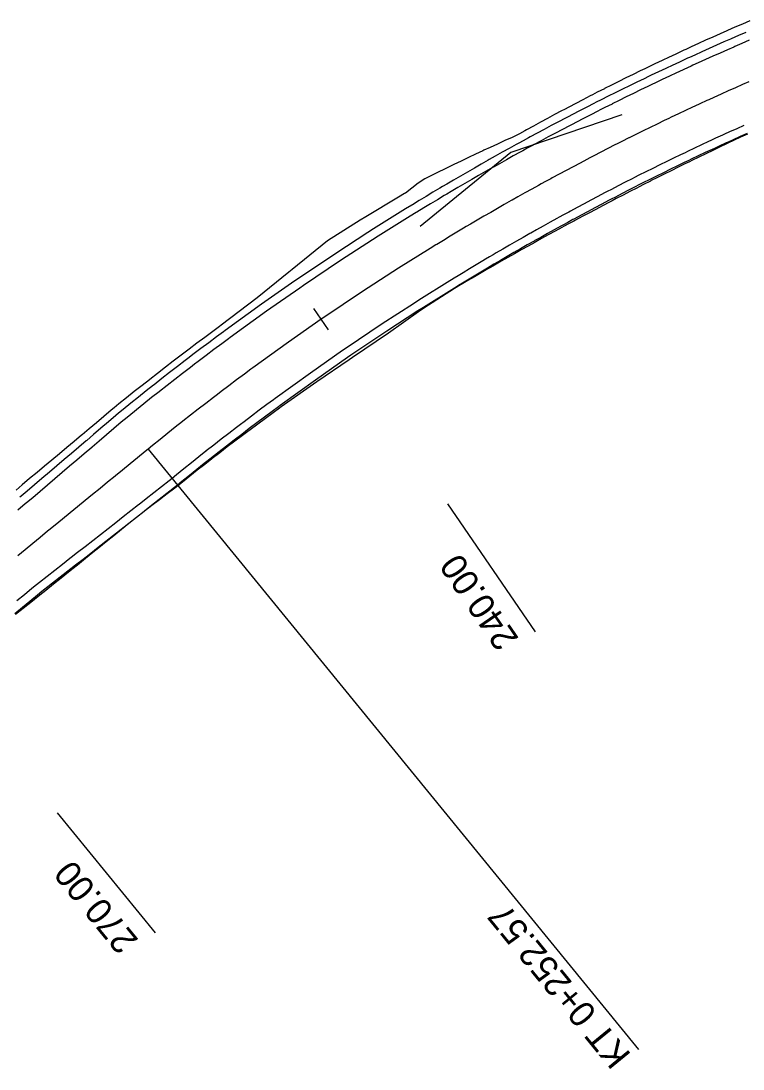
# Model space of a CAD drawing. Extents: x -550605 to -538780, y -1102367 to -1093705.
# Drawn here: x -546697.9 to -546656, y -1100798.1 to -1100737.2 of the extents above; entities that cross this region are included whole.
import ezdxf

# ---------------------------------------------------------------- set-up
doc = ezdxf.new("R2010")
doc.units = 0
for name, color, linetype in [('SIT - horní hrana zářezu', 7, 'Continuous'), ('SIT - hrany vozovky', 7, 'Continuous'), ('SIT - osa cesty', 7, 'Continuous'), ('SIT - paty násypů', 7, 'Continuous'), ('SIT - poloměry oblouků', 7, 'Continuous'), ('SIT - staničení hlavních bodů', 7, 'Continuous'), ('SIT - staničení po 30m', 7, 'Continuous')]:
    doc.layers.add(name, color=color, linetype=linetype)

msp = doc.modelspace()

# ---------------------------------------------------------------- linework, layer by layer
at = {"layer": 'SIT - horní hrana zářezu'}
msp.add_lwpolyline([(-546672.732, -1100752.748), (-546674.519, -1100753.888), (-546674.825, -1100754.101), (-546676.572, -1100755.346), (-546678.653, -1100756.758), (-546678.859, -1100756.895), (-546680.737, -1100758.166), (-546682.793, -1100759.616), (-546682.893, -1100759.688), (-546683.273, -1100759.963), (-546683.719, -1100760.289), (-546684.163, -1100760.616), (-546684.606, -1100760.945), (-546684.821, -1100761.106), (-546685.048, -1100761.276), (-546685.488, -1100761.608), (-546685.928, -1100761.942), (-546686.366, -1100762.278), (-546686.802, -1100762.616), (-546686.82, -1100762.63), (-546686.822, -1100762.632), (-546687.237, -1100762.955), (-546687.671, -1100763.296), (-546688.104, -1100763.639), (-546688.535, -1100763.983), (-546688.796, -1100764.193), (-546688.972, -1100764.328), (-546689.419, -1100764.669), (-546689.866, -1100765.01), (-546690.314, -1100765.351), (-546690.732, -1100765.67), (-546690.761, -1100765.692)], dxfattribs=at)
at = {"layer": 'SIT - hrany vozovky'}
for points in [[(-546655.619, -1100738.343), (-546656.044, -1100738.526), (-546656.468, -1100738.711), (-546656.517, -1100738.732), (-546656.892, -1100738.896), (-546657.315, -1100739.083), (-546657.737, -1100739.272), (-546658.159, -1100739.461), (-546658.581, -1100739.652), (-546658.892, -1100739.794), (-546659.001, -1100739.844), (-546659.422, -1100740.037), (-546659.713, -1100740.172), (-546659.841, -1100740.232), (-546660.26, -1100740.428), (-546660.678, -1100740.625), (-546661.096, -1100740.824), (-546661.248, -1100740.896), (-546661.513, -1100741.023), (-546661.93, -1100741.224), (-546662.346, -1100741.427), (-546662.761, -1100741.63), (-546663.176, -1100741.835), (-546663.585, -1100742.038), (-546663.59, -1100742.041), (-546664.004, -1100742.248), (-546664.277, -1100742.386), (-546664.416, -1100742.457), (-546664.829, -1100742.667), (-546665.24, -1100742.878), (-546665.651, -1100743.09), (-546665.903, -1100743.221), (-546666.061, -1100743.303), (-546666.471, -1100743.518), (-546666.88, -1100743.734), (-546667.288, -1100743.952), (-546667.696, -1100744.17), (-546668.103, -1100744.39), (-546668.199, -1100744.442), (-546668.509, -1100744.611), (-546668.765, -1100744.751), (-546668.915, -1100744.833), (-546669.32, -1100745.057), (-546669.724, -1100745.281), (-546670.128, -1100745.507), (-546670.475, -1100745.703), (-546670.531, -1100745.734), (-546670.933, -1100745.963), (-546671.334, -1100746.192), (-546671.735, -1100746.423), (-546672.135, -1100746.655), (-546672.535, -1100746.888), (-546672.729, -1100747.002), (-546672.933, -1100747.123), (-546673.172, -1100747.264), (-546673.331, -1100747.358), (-546673.729, -1100747.595), (-546674.125, -1100747.833), (-546674.521, -1100748.073), (-546674.916, -1100748.313), (-546674.96, -1100748.34), (-546675.311, -1100748.555), (-546677.168, -1100749.715), (-546677.493, -1100749.923), (-546679.352, -1100751.129), (-546681.511, -1100752.579), (-546681.723, -1100752.724), (-546683.646, -1100754.066), (-546685.755, -1100755.589), (-546685.857, -1100755.664), (-546686.247, -1100755.953), (-546686.705, -1100756.294), (-546687.161, -1100756.636), (-546687.616, -1100756.98), (-546687.837, -1100757.148), (-546688.07, -1100757.326), (-546688.522, -1100757.673), (-546688.973, -1100758.023), (-546689.423, -1100758.373), (-546689.872, -1100758.726), (-546689.89, -1100758.741), (-546689.893, -1100758.743), (-546690.319, -1100759.08), (-546690.765, -1100759.436), (-546691.209, -1100759.794), (-546691.652, -1100760.153), (-546691.921, -1100760.372), (-546692.089, -1100760.515), (-546692.517, -1100760.88), (-546692.945, -1100761.244), (-546693.373, -1100761.609), (-546693.774, -1100761.95), (-546693.802, -1100761.973), (-546694.23, -1100762.338), (-546694.658, -1100762.703), (-546695.086, -1100763.067), (-546695.514, -1100763.432), (-546695.942, -1100763.796), (-546696.37, -1100764.161), (-546696.799, -1100764.525), (-546697.227, -1100764.89), (-546697.581, -1100765.192), (-546697.655, -1100765.255), (-546698.083, -1100765.619)], [(-546655.816, -1100737.884), (-546656.243, -1100738.068), (-546656.668, -1100738.252), (-546656.717, -1100738.274), (-546657.093, -1100738.439), (-546657.518, -1100738.626), (-546657.942, -1100738.815), (-546658.365, -1100739.005), (-546658.788, -1100739.197), (-546659.1, -1100739.339), (-546659.21, -1100739.389), (-546659.631, -1100739.583), (-546659.923, -1100739.719), (-546660.052, -1100739.779), (-546660.473, -1100739.975), (-546660.892, -1100740.173), (-546661.311, -1100740.372), (-546661.464, -1100740.445), (-546661.73, -1100740.573), (-546662.148, -1100740.774), (-546662.565, -1100740.977), (-546662.982, -1100741.181), (-546663.398, -1100741.387), (-546663.809, -1100741.591), (-546663.814, -1100741.594), (-546664.228, -1100741.802), (-546664.503, -1100741.94), (-546664.643, -1100742.011), (-546665.056, -1100742.221), (-546665.469, -1100742.433), (-546665.881, -1100742.646), (-546666.134, -1100742.777), (-546666.293, -1100742.86), (-546666.704, -1100743.076), (-546667.114, -1100743.293), (-546667.524, -1100743.511), (-546667.933, -1100743.73), (-546668.341, -1100743.95), (-546668.438, -1100744.003), (-546668.749, -1100744.172), (-546669.006, -1100744.313), (-546669.156, -1100744.395), (-546669.562, -1100744.619), (-546669.968, -1100744.845), (-546670.373, -1100745.071), (-546670.721, -1100745.268), (-546670.777, -1100745.299), (-546671.18, -1100745.528), (-546671.583, -1100745.759), (-546671.985, -1100745.99), (-546672.387, -1100746.223), (-546672.788, -1100746.457), (-546672.982, -1100746.571), (-546673.188, -1100746.692), (-546673.427, -1100746.834), (-546673.587, -1100746.929), (-546673.985, -1100747.166), (-546674.383, -1100747.405), (-546674.78, -1100747.645), (-546675.177, -1100747.886), (-546675.221, -1100747.913), (-546675.572, -1100748.129), (-546677.436, -1100749.293), (-546677.762, -1100749.501), (-546679.627, -1100750.711), (-546681.794, -1100752.166), (-546682.006, -1100752.311), (-546683.935, -1100753.658), (-546686.051, -1100755.186), (-546686.153, -1100755.262), (-546686.545, -1100755.551), (-546687.004, -1100755.893), (-546687.462, -1100756.237), (-546687.919, -1100756.582), (-546688.14, -1100756.75), (-546688.374, -1100756.929), (-546688.828, -1100757.277), (-546689.28, -1100757.628), (-546689.732, -1100757.98), (-546690.182, -1100758.334), (-546690.2, -1100758.348), (-546690.203, -1100758.35), (-546690.63, -1100758.689), (-546691.077, -1100759.046), (-546691.523, -1100759.405), (-546691.968, -1100759.765), (-546692.237, -1100759.985), (-546692.405, -1100760.128), (-546692.834, -1100760.493), (-546693.262, -1100760.857), (-546693.69, -1100761.222), (-546694.09, -1100761.563), (-546694.118, -1100761.586), (-546694.546, -1100761.951), (-546694.974, -1100762.316), (-546695.402, -1100762.68), (-546695.831, -1100763.045), (-546696.259, -1100763.409), (-546696.687, -1100763.774), (-546697.115, -1100764.138), (-546697.543, -1100764.503), (-546697.898, -1100764.805), (-546697.971, -1100764.868)], [(-546655.736, -1100743.744), (-546656.145, -1100743.928), (-546656.552, -1100744.112), (-546656.854, -1100744.25), (-546656.96, -1100744.298), (-546657.366, -1100744.486), (-546657.648, -1100744.616), (-546657.772, -1100744.674), (-546658.178, -1100744.864), (-546658.583, -1100745.054), (-546658.987, -1100745.246), (-546659.134, -1100745.317), (-546659.391, -1100745.44), (-546659.794, -1100745.634), (-546660.197, -1100745.83), (-546660.599, -1100746.027), (-546661, -1100746.225), (-546661.396, -1100746.422), (-546661.401, -1100746.425), (-546661.801, -1100746.625), (-546662.066, -1100746.759), (-546662.2, -1100746.827), (-546662.599, -1100747.03), (-546662.998, -1100747.234), (-546663.395, -1100747.44), (-546663.639, -1100747.566), (-546663.792, -1100747.646), (-546664.189, -1100747.854), (-546664.585, -1100748.063), (-546664.98, -1100748.274), (-546665.374, -1100748.485), (-546665.768, -1100748.698), (-546665.862, -1100748.749), (-546666.161, -1100748.912), (-546666.409, -1100749.047), (-546666.554, -1100749.127), (-546666.946, -1100749.343), (-546667.337, -1100749.561), (-546667.728, -1100749.779), (-546668.064, -1100749.969), (-546668.118, -1100749.999), (-546668.507, -1100750.22), (-546668.896, -1100750.442), (-546669.284, -1100750.666), (-546669.671, -1100750.89), (-546670.057, -1100751.116), (-546670.245, -1100751.226), (-546670.443, -1100751.343), (-546670.674, -1100751.48), (-546670.828, -1100751.571), (-546671.213, -1100751.8), (-546671.597, -1100752.031), (-546671.98, -1100752.262), (-546672.362, -1100752.495), (-546672.404, -1100752.521), (-546672.744, -1100752.729), (-546674.541, -1100753.852), (-546674.856, -1100754.052), (-546676.655, -1100755.22), (-546678.745, -1100756.623), (-546678.95, -1100756.763), (-546680.811, -1100758.062), (-546682.852, -1100759.537), (-546682.95, -1100759.609), (-546683.328, -1100759.889), (-546683.771, -1100760.218), (-546684.213, -1100760.55), (-546684.653, -1100760.883), (-546684.867, -1100761.045), (-546685.092, -1100761.217), (-546685.53, -1100761.554), (-546685.967, -1100761.892), (-546686.402, -1100762.231), (-546686.836, -1100762.572), (-546686.854, -1100762.587), (-546686.856, -1100762.588), (-546687.269, -1100762.915), (-546687.7, -1100763.26), (-546688.131, -1100763.606), (-546688.559, -1100763.954), (-546688.819, -1100764.165), (-546688.993, -1100764.302), (-546689.435, -1100764.649), (-546689.878, -1100764.996), (-546690.32, -1100765.343), (-546690.734, -1100765.668), (-546690.763, -1100765.69), (-546691.205, -1100766.038), (-546691.647, -1100766.385), (-546692.09, -1100766.732), (-546692.532, -1100767.079), (-546692.974, -1100767.426), (-546693.417, -1100767.773), (-546693.859, -1100768.121), (-546694.302, -1100768.468), (-546694.668, -1100768.755), (-546694.744, -1100768.815), (-546695.186, -1100769.162), (-546695.629, -1100769.509), (-546696.071, -1100769.856), (-546696.514, -1100770.204), (-546696.688, -1100770.34), (-546696.952, -1100770.556), (-546697.387, -1100770.912), (-546697.822, -1100771.268), (-546698.257, -1100771.624)], [(-546655.941, -1100743.288), (-546656.35, -1100743.472), (-546656.759, -1100743.657), (-546657.062, -1100743.795), (-546657.168, -1100743.844), (-546657.576, -1100744.032), (-546657.859, -1100744.163), (-546657.983, -1100744.221), (-546658.39, -1100744.411), (-546658.797, -1100744.602), (-546659.202, -1100744.795), (-546659.35, -1100744.866), (-546659.607, -1100744.989), (-546660.012, -1100745.184), (-546660.416, -1100745.381), (-546660.819, -1100745.578), (-546661.222, -1100745.777), (-546661.62, -1100745.975), (-546661.624, -1100745.977), (-546662.026, -1100746.179), (-546662.291, -1100746.313), (-546662.427, -1100746.381), (-546662.827, -1100746.585), (-546663.227, -1100746.79), (-546663.626, -1100746.996), (-546663.87, -1100747.123), (-546664.024, -1100747.203), (-546664.422, -1100747.412), (-546664.819, -1100747.622), (-546665.215, -1100747.833), (-546665.611, -1100748.045), (-546666.006, -1100748.258), (-546666.1, -1100748.309), (-546666.401, -1100748.473), (-546666.65, -1100748.609), (-546666.795, -1100748.689), (-546667.188, -1100748.906), (-546667.581, -1100749.124), (-546667.973, -1100749.343), (-546668.31, -1100749.533), (-546668.364, -1100749.564), (-546668.755, -1100749.786), (-546669.144, -1100750.009), (-546669.534, -1100750.233), (-546669.922, -1100750.458), (-546670.31, -1100750.685), (-546670.498, -1100750.795), (-546670.697, -1100750.912), (-546670.929, -1100751.049), (-546671.084, -1100751.141), (-546671.47, -1100751.371), (-546671.855, -1100751.602), (-546672.239, -1100751.835), (-546672.623, -1100752.068), (-546672.665, -1100752.094), (-546673.006, -1100752.303), (-546674.809, -1100753.43), (-546675.125, -1100753.631), (-546676.93, -1100754.802), (-546679.027, -1100756.211), (-546679.233, -1100756.351), (-546681.1, -1100757.655), (-546683.148, -1100759.134), (-546683.247, -1100759.207), (-546683.626, -1100759.487), (-546684.071, -1100759.818), (-546684.514, -1100760.15), (-546684.956, -1100760.485), (-546685.17, -1100760.648), (-546685.396, -1100760.82), (-546685.836, -1100761.158), (-546686.274, -1100761.497), (-546686.71, -1100761.838), (-546687.146, -1100762.18), (-546687.164, -1100762.194), (-546687.166, -1100762.196), (-546687.58, -1100762.524), (-546688.013, -1100762.87), (-546688.445, -1100763.217), (-546688.875, -1100763.566), (-546689.136, -1100763.778), (-546689.31, -1100763.915), (-546689.752, -1100764.262), (-546690.194, -1100764.609), (-546690.637, -1100764.956), (-546691.05, -1100765.281), (-546691.079, -1100765.303), (-546691.521, -1100765.651), (-546691.964, -1100765.998), (-546692.406, -1100766.345), (-546692.849, -1100766.692), (-546693.291, -1100767.039), (-546693.733, -1100767.386), (-546694.176, -1100767.734), (-546694.618, -1100768.081), (-546694.984, -1100768.368), (-546695.061, -1100768.428), (-546695.503, -1100768.775), (-546695.945, -1100769.122), (-546696.388, -1100769.469), (-546696.83, -1100769.816), (-546697.004, -1100769.953), (-546697.268, -1100770.169), (-546697.703, -1100770.525), (-546698.139, -1100770.881)]]:
    msp.add_lwpolyline(points, dxfattribs=at)
at = {"layer": 'SIT - osa cesty'}
msp.add_lwpolyline([(-546655.636, -1100740.748), (-546656.006, -1100740.91), (-546656.423, -1100741.094), (-546656.839, -1100741.28), (-546657.255, -1100741.467), (-546657.67, -1100741.655), (-546657.977, -1100741.795), (-546658.085, -1100741.844), (-546658.499, -1100742.035), (-546658.786, -1100742.167), (-546658.912, -1100742.226), (-546659.325, -1100742.419), (-546659.738, -1100742.614), (-546660.149, -1100742.809), (-546660.299, -1100742.881), (-546660.56, -1100743.006), (-546660.971, -1100743.204), (-546661.381, -1100743.404), (-546661.79, -1100743.604), (-546662.199, -1100743.806), (-546662.602, -1100744.007), (-546662.607, -1100744.009), (-546663.015, -1100744.213), (-546663.284, -1100744.349), (-546663.422, -1100744.419), (-546663.828, -1100744.626), (-546664.233, -1100744.834), (-546664.638, -1100745.043), (-546664.886, -1100745.172), (-546665.043, -1100745.253), (-546665.446, -1100745.465), (-546665.849, -1100745.678), (-546666.252, -1100745.892), (-546666.654, -1100746.107), (-546667.055, -1100746.324), (-546667.15, -1100746.376), (-546667.455, -1100746.542), (-546667.708, -1100746.68), (-546667.855, -1100746.761), (-546668.254, -1100746.981), (-546668.652, -1100747.203), (-546669.05, -1100747.425), (-546669.392, -1100747.618), (-546669.447, -1100747.649), (-546669.844, -1100747.874), (-546670.239, -1100748.1), (-546670.634, -1100748.328), (-546671.029, -1100748.557), (-546671.422, -1100748.786), (-546671.614, -1100748.899), (-546671.815, -1100749.018), (-546672.051, -1100749.157), (-546672.208, -1100749.25), (-546672.599, -1100749.483), (-546672.99, -1100749.718), (-546673.38, -1100749.954), (-546673.769, -1100750.191), (-546673.812, -1100750.217), (-546674.158, -1100750.429), (-546675.988, -1100751.573), (-546676.309, -1100751.777), (-546678.141, -1100752.965), (-546680.269, -1100754.395), (-546680.478, -1100754.537), (-546682.373, -1100755.86), (-546684.451, -1100757.361), (-546684.552, -1100757.435), (-546684.937, -1100757.72), (-546685.388, -1100758.056), (-546685.838, -1100758.393), (-546686.286, -1100758.732), (-546686.504, -1100758.898), (-546686.733, -1100759.073), (-546687.179, -1100759.416), (-546687.624, -1100759.76), (-546688.067, -1100760.106), (-546688.509, -1100760.453), (-546688.527, -1100760.468), (-546688.529, -1100760.469), (-546688.95, -1100760.802), (-546689.389, -1100761.153), (-546689.827, -1100761.505), (-546690.264, -1100761.859), (-546690.528, -1100762.075), (-546690.699, -1100762.215), (-546691.135, -1100762.571), (-546691.57, -1100762.927), (-546692.005, -1100763.283), (-546692.412, -1100763.615), (-546692.44, -1100763.638), (-546692.876, -1100763.994), (-546693.311, -1100764.35), (-546693.746, -1100764.706), (-546694.181, -1100765.062), (-546694.617, -1100765.418), (-546695.052, -1100765.774), (-546695.487, -1100766.129), (-546695.922, -1100766.485), (-546696.283, -1100766.78), (-546696.358, -1100766.841), (-546696.793, -1100767.197), (-546697.228, -1100767.553), (-546697.663, -1100767.909), (-546698.099, -1100768.265)], dxfattribs=at)
at = {"layer": 'SIT - paty násypů'}
for points in [[(-546655.595, -1100737.22), (-546656.023, -1100737.404), (-546656.45, -1100737.589), (-546656.876, -1100737.775), (-546656.926, -1100737.797), (-546657.302, -1100737.963), (-546657.728, -1100738.153), (-546658.153, -1100738.344), (-546658.577, -1100738.536), (-546659, -1100738.73), (-546659.313, -1100738.874), (-546659.423, -1100738.925), (-546659.845, -1100739.122), (-546660.137, -1100739.259), (-546660.266, -1100739.32), (-546660.687, -1100739.518), (-546661.108, -1100739.717), (-546661.528, -1100739.918), (-546661.681, -1100739.991), (-546661.948, -1100740.119), (-546662.367, -1100740.323), (-546662.785, -1100740.527), (-546663.202, -1100740.734), (-546663.619, -1100740.942), (-546664.03, -1100741.149), (-546664.034, -1100741.151), (-546664.449, -1100741.362), (-546664.724, -1100741.503), (-546664.864, -1100741.575), (-546665.277, -1100741.789), (-546665.69, -1100742.004), (-546666.103, -1100742.219), (-546666.355, -1100742.353), (-546666.514, -1100742.437), (-546666.925, -1100742.656), (-546667.335, -1100742.876), (-546667.744, -1100743.098), (-546668.153, -1100743.321), (-546668.561, -1100743.545), (-546668.657, -1100743.599), (-546668.967, -1100743.771), (-546669.23, -1100743.904), (-546669.387, -1100743.975), (-546669.812, -1100744.168), (-546670.237, -1100744.362), (-546670.661, -1100744.558), (-546671.026, -1100744.728), (-546671.085, -1100744.755), (-546671.508, -1100744.954), (-546671.93, -1100745.153), (-546672.353, -1100745.355), (-546672.774, -1100745.557), (-546673.195, -1100745.761), (-546673.4, -1100745.861), (-546673.616, -1100745.966), (-546673.868, -1100746.09), (-546674.036, -1100746.173), (-546674.455, -1100746.381), (-546674.852, -1100746.627), (-546675.22, -1100746.921), (-546675.59, -1100747.21), (-546675.634, -1100747.236), (-546675.991, -1100747.448), (-546677.883, -1100748.588), (-546678.215, -1100748.792), (-546680.113, -1100749.974), (-546682.153, -1100751.641), (-546682.356, -1100751.802), (-546684.196, -1100753.291), (-546686.278, -1100754.878), (-546686.38, -1100754.953), (-546686.773, -1100755.244), (-546687.233, -1100755.587), (-546687.693, -1100755.931), (-546688.151, -1100756.276), (-546688.373, -1100756.445), (-546688.607, -1100756.623), (-546689.063, -1100756.972), (-546689.518, -1100757.322), (-546689.972, -1100757.673), (-546690.424, -1100758.026), (-546690.443, -1100758.041), (-546690.445, -1100758.043), (-546690.875, -1100758.38), (-546691.326, -1100758.736), (-546691.775, -1100759.093), (-546692.223, -1100759.452), (-546692.494, -1100759.671), (-546692.663, -1100759.813), (-546693.093, -1100760.175), (-546693.524, -1100760.537), (-546693.954, -1100760.898), (-546694.357, -1100761.236), (-546694.385, -1100761.26), (-546694.816, -1100761.621), (-546695.247, -1100761.982), (-546695.678, -1100762.343), (-546696.109, -1100762.704), (-546696.54, -1100763.065), (-546696.972, -1100763.425), (-546697.403, -1100763.786), (-546697.835, -1100764.146), (-546698.193, -1100764.444)], [(-546655.719, -1100743.784), (-546656.125, -1100743.972), (-546656.53, -1100744.161), (-546656.83, -1100744.302), (-546656.935, -1100744.352), (-546657.34, -1100744.543), (-546657.62, -1100744.676), (-546657.744, -1100744.735), (-546658.147, -1100744.929), (-546658.55, -1100745.123), (-546658.953, -1100745.318), (-546659.099, -1100745.39), (-546659.355, -1100745.515), (-546659.756, -1100745.712), (-546660.158, -1100745.91), (-546660.558, -1100746.109), (-546660.958, -1100746.309), (-546661.353, -1100746.508), (-546661.358, -1100746.511), (-546661.757, -1100746.713), (-546662.021, -1100746.847), (-546662.155, -1100746.916), (-546662.553, -1100747.12), (-546662.95, -1100747.326), (-546663.347, -1100747.533), (-546663.59, -1100747.66), (-546663.743, -1100747.741), (-546664.139, -1100747.95), (-546664.534, -1100748.159), (-546664.93, -1100748.368), (-546665.325, -1100748.577), (-546665.719, -1100748.788), (-546665.813, -1100748.838), (-546666.113, -1100749), (-546666.362, -1100749.134), (-546666.507, -1100749.213), (-546666.9, -1100749.426), (-546667.292, -1100749.641), (-546667.684, -1100749.856), (-546668.022, -1100750.043), (-546668.076, -1100750.073), (-546668.467, -1100750.291), (-546668.857, -1100750.509), (-546669.247, -1100750.729), (-546669.636, -1100750.949), (-546670.025, -1100751.171), (-546670.214, -1100751.279), (-546670.414, -1100751.393), (-546670.646, -1100751.527), (-546670.801, -1100751.616), (-546671.189, -1100751.841), (-546671.575, -1100752.066), (-546671.961, -1100752.292), (-546672.347, -1100752.52), (-546672.39, -1100752.545), (-546672.732, -1100752.748)], [(-546690.761, -1100765.692), (-546691.202, -1100766.041), (-546691.64, -1100766.393), (-546692.078, -1100766.746), (-546692.517, -1100767.098), (-546692.955, -1100767.451), (-546693.393, -1100767.803), (-546693.831, -1100768.155), (-546694.269, -1100768.508), (-546694.632, -1100768.8), (-546694.707, -1100768.86), (-546695.145, -1100769.213), (-546695.582, -1100769.566), (-546696.02, -1100769.919), (-546696.457, -1100770.272), (-546696.633, -1100770.407), (-546696.901, -1100770.618), (-546697.342, -1100770.967), (-546697.782, -1100771.317), (-546698.223, -1100771.666)]]:
    msp.add_lwpolyline(points, dxfattribs=at)
at = {"layer": 'SIT - poloměry oblouků'}
msp.add_lwpolyline([(-546663.016, -1100742.669), (-546669.46, -1100744.85), (-546674.727, -1100749.156)], dxfattribs=at)
at = {"layer": 'SIT - staničení hlavních bodů'}
msp.add_lwpolyline([(-546690.528, -1100762.075), (-546662.045, -1100796.913)], dxfattribs=at)
at = {"layer": 'SIT - staničení po 30m'}
for points in [[(-546680.053, -1100755.156), (-546680.902, -1100753.919)], [(-546668.027, -1100772.675), (-546673.12, -1100765.255)], [(-546690.1, -1100790.142), (-546695.796, -1100783.174)]]:
    msp.add_lwpolyline(points, dxfattribs=at)

# ---------------------------------------------------------------- texts
at = {"layer": 'SIT - staničení hlavních bodů'}
msp.add_text('KT 0+252.57', height=1.5, rotation=129.26901, dxfattribs=at).set_placement((-546662.432, -1100797.23))
at = {"layer": 'SIT - staničení po 30m'}
for s, rotation, p in [('240.00', 124.4689, (-546668.967, -1100773.071)), ('270.00', 129.26901, (-546691.041, -1100790.57))]:
    msp.add_text(s, height=1.5, rotation=rotation, dxfattribs=at).set_placement(p)

doc.saveas('drawing.dxf')
